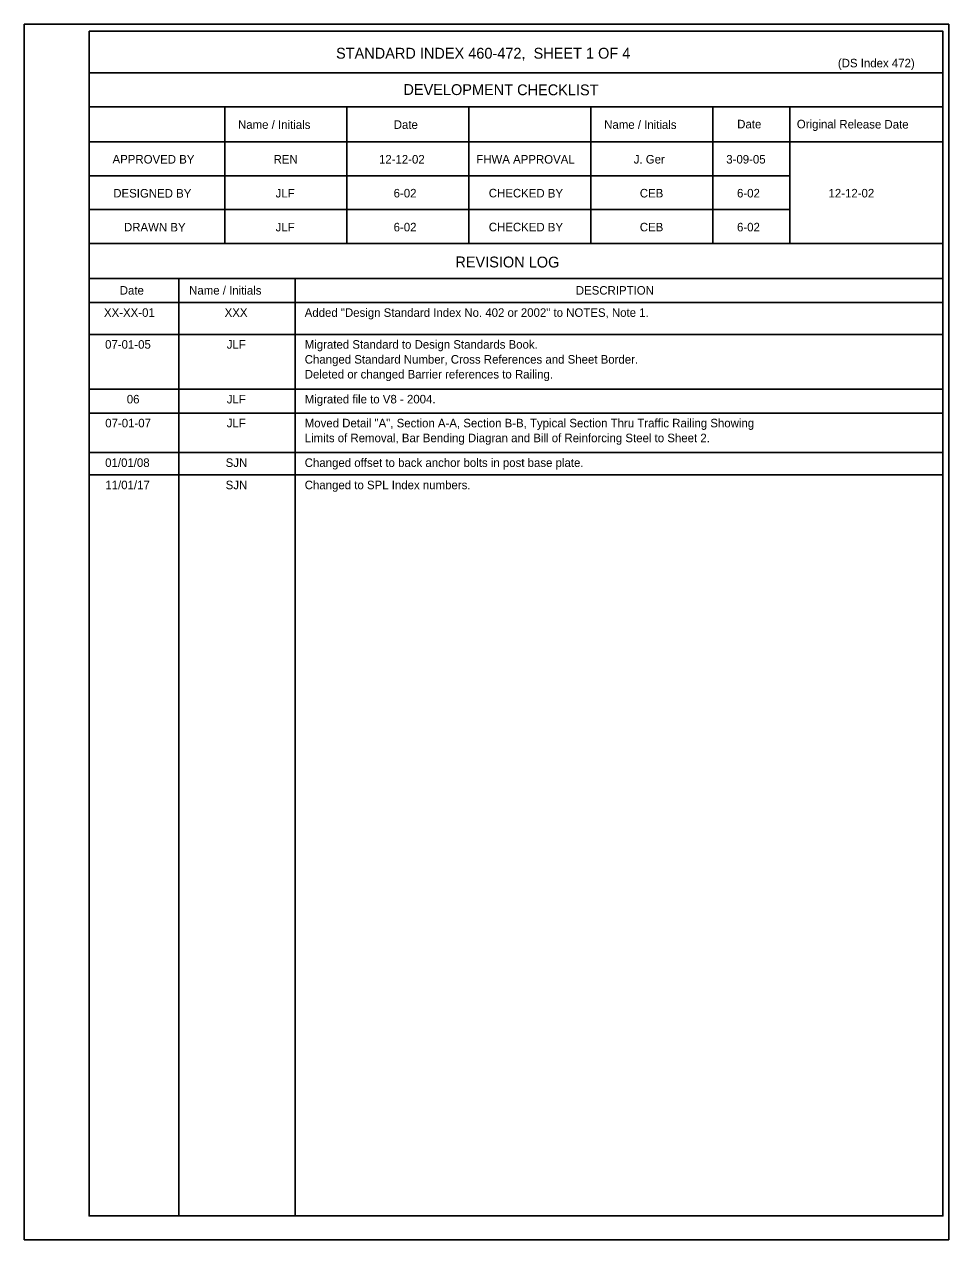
# Model space of a CAD drawing. Extents: x 21516.9 to 21586.2, y 56154.4 to 56193.6.
# Drawn here: x 21564.41 to 21586.23, y 56162.48 to 56191.15 of the extents above; entities that cross this region are included whole.
import ezdxf

# ---------------------------------------------------------------- set-up
doc = ezdxf.new("R2010")
doc.units = 0
for name, color, linetype in [('PlotBorder_dp', 7, 'Continuous'), ('SheetBorder_dp', 7, 'Continuous'), ('SheetLines_dp', 7, 'Continuous')]:
    doc.layers.add(name, color=color, linetype=linetype)

msp = doc.modelspace()

# ---------------------------------------------------------------- linework, layer by layer
at = {"layer": 'PlotBorder_dp'}
for p, q in [((21565.943, 56183.838), (21586.09, 56183.838)), ((21565.944, 56182.547), (21586.09, 56182.547)), ((21565.944, 56181.983), (21586.09, 56181.983)), ((21565.944, 56181.049), (21586.09, 56181.049)), ((21565.944, 56180.523), (21586.09, 56180.523)), ((21564.413, 56162.485), (21564.413, 56162.485))]:
    msp.add_line(p, q, dxfattribs=at)
msp.add_lwpolyline([(21564.413, 56191.151), (21586.226, 56191.151), (21586.226, 56162.485), (21564.413, 56162.485)], close=True, dxfattribs=at)
at = {"layer": 'SheetLines_dp'}
for p, q in [((21586.09, 56190.008), (21565.943, 56190.008)), ((21586.09, 56189.208), (21565.943, 56189.208)), ((21569.143, 56189.208), (21569.143, 56185.98)), ((21572.023, 56189.208), (21572.023, 56185.98)), ((21574.903, 56189.208), (21574.903, 56185.98)), ((21577.783, 56189.208), (21577.783, 56185.98)), ((21580.663, 56189.208), (21580.663, 56185.98)), ((21582.478, 56189.208), (21582.478, 56185.98)), ((21586.09, 56188.38), (21565.943, 56188.38)), ((21582.478, 56187.58), (21565.943, 56187.58)), ((21582.478, 56186.78), (21565.943, 56186.78)), ((21586.09, 56185.98), (21565.943, 56185.98)), ((21586.09, 56185.152), (21565.943, 56185.152)), ((21568.063, 56185.152), (21568.063, 56163.046)), ((21570.806, 56185.152), (21570.806, 56163.046)), ((21586.09, 56184.589), (21565.943, 56184.589))]:
    msp.add_line(p, q, dxfattribs=at)
msp.add_lwpolyline([(21565.943, 56190.989), (21586.09, 56190.989), (21586.09, 56163.046), (21565.943, 56163.046)], close=True, dxfattribs=at)

# ---------------------------------------------------------------- texts
at = {"layer": 'SheetBorder_dp'}
for s, height, p in [('STANDARD INDEX 460-472,  SHEET 1 OF 4', 0.256, (21571.769, 56190.341)), ('(DS Index 472)', 0.2016, (21583.611, 56190.136)), ('REN', 0.2016, (21570.295, 56187.867)), ('12-12-02', 0.2016, (21572.782, 56187.867)), ('J. Ger', 0.2016, (21578.793, 56187.867)), ('3-09-05', 0.2016, (21580.977, 56187.867)), ('JLF', 0.2016, (21570.343, 56187.067)), ('6-02', 0.2016, (21573.128, 56187.067)), ('CEB', 0.2016, (21578.937, 56187.067)), ('6-02', 0.2016, (21581.231, 56187.067)), ('12-12-02', 0.2016, (21583.39, 56187.067)), ('JLF', 0.2016, (21570.343, 56186.267)), ('6-02', 0.2016, (21573.128, 56186.267)), ('CEB', 0.2016, (21578.937, 56186.267)), ('6-02', 0.2016, (21581.231, 56186.267)), ('DESCRIPTION', 0.2016, (21577.427, 56184.775)), ('XX-XX-01', 0.2016, (21566.293, 56184.251)), ('XXX', 0.2016, (21569.14, 56184.251)), ('Added "Design Standard Index No. 402 or 2002" to NOTES, Note 1. ', 0.2016, (21571.029, 56184.251)), ('07-01-05', 0.2016, (21566.319, 56183.5)), ('JLF', 0.2016, (21569.19, 56183.5)), ('Migrated Standard to Design Standards Book.', 0.2016, (21571.03, 56183.5)), ('Changed Standard Number, Cross References and Sheet Border.', 0.2016, (21571.03, 56183.148)), ('Deleted or changed Barrier references to Railing.', 0.2016, (21571.03, 56182.797)), ('06', 0.2016, (21566.831, 56182.209)), ('JLF', 0.2016, (21569.19, 56182.209)), ('Migrated file to V8 - 2004.', 0.2016, (21571.03, 56182.209)), ('07-01-07', 0.2016, (21566.323, 56181.645)), ('JLF', 0.2016, (21569.19, 56181.645)), ('Moved Detail "A", Section A-A, Section B-B, Typical Section Thru Traffic Railing Showing ', 0.2016, (21571.03, 56181.645)), ('Limits of Removal, Bar Bending Diagran and Bill of Reinforcing Steel to Sheet 2.', 0.2016, (21571.03, 56181.294)), ('01/01/08', 0.2016, (21566.321, 56180.711)), ('SJN', 0.2016, (21569.165, 56180.711)), ('Changed offset to back anchor bolts in post base plate.', 0.2016, (21571.03, 56180.711)), ('11/01/17', 0.2016, (21566.325, 56180.185)), ('SJN', 0.2016, (21569.165, 56180.185)), ('Changed to SPL Index numbers.', 0.2016, (21571.03, 56180.185))]:
    msp.add_text(s, height=height, dxfattribs=at).set_placement(p)
for s, height, p in [('DEVELOPMENT CHECKLIST', 0.256, (21573.359, 56189.485)), ('Name / Initials', 0.2016, (21569.456, 56188.687)), ('Date', 0.2016, (21573.13, 56188.685)), ('Name / Initials', 0.2016, (21578.096, 56188.687)), ('Date', 0.2016, (21581.235, 56188.697)), ('Original Release Date', 0.2016, (21582.642, 56188.697)), ('APPROVED BY', 0.2016, (21566.495, 56187.869)), ('FHWA APPROVAL', 0.2016, (21575.078, 56187.869)), ('DESIGNED BY', 0.2016, (21566.512, 56187.067)), ('CHECKED BY', 0.2016, (21575.373, 56187.069)), ('DRAWN BY', 0.2016, (21566.765, 56186.267)), ('CHECKED BY', 0.2016, (21575.373, 56186.269)), ('REVISION LOG', 0.256, (21574.584, 56185.419)), ('Date', 0.2016, (21566.665, 56184.776)), ('Name / Initials', 0.2016, (21568.302, 56184.778))]:
    msp.add_text(s, height=height, rotation=359.8756, dxfattribs=at).set_placement(p)

doc.saveas('drawing.dxf')
